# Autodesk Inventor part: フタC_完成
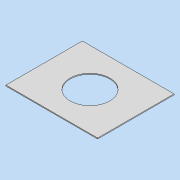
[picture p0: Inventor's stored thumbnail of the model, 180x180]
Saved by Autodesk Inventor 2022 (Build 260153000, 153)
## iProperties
Created: 2021-07
Part Number: フタC_完成
Material: 一般
Document SubType Name: Modeling
Designer: DesignLab
Density: 1 g/cm^3
Appearance: 既定
Author: DesignLab
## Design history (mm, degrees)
sketch "スケッチ1"
  geometry: L1 (150, -125)-(-150, -125); L2 (-150, -125)-(-150, 125); L3 (-150, 125)-(150, 125); L4 (150, 125)-(150, -125); L5 (150, -125)-(-150, 125); L6 (-150, -125)-(150, 125); 1 further point
  constraints: 12 end point, 2 midpoint, 2 parallel, 1 horizontal, 1 perpendicular
  dimensions: "d0" = 300 distance of L2.end L3.end; "d1" = 250 distance of L1.end L2.end
extrude "押し出し1" new body sketch "スケッチ1" distance "d2" = 3; taper "d3" = 0 deg
sketch "スケッチ2"
  geometry: C1 r 65 at (0, 0); 1 further point
  constraints: 1 centre point, 1 coincident
  dimensions: "d4" = 130 diameter of C1
extrude "押し出し2" cut sketch "スケッチ2" extent not by distance; stored distance "d5" = 0; taper "d6" = 0 deg
node "ソリッド1"
